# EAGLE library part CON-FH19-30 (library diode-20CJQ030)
Hirose FH19 & FH19S Series 0.5mm pitch, 0.9mm above the board, Flexible Printed Circuit & Flexible Flat Cable Connectors Features: 1. Low-profile 0.5mm pitch FPC, FFC Connectors Miniaturization of portable equipment and personal mobile devices has created increased demand for a low profile, high density, and high reliability connectors. *The design of this connector has been made thinner and smaller, with a height of 0.9mm and width of 3mm. [As of August 2002, this is the smallest connector of this type available on the market !] *PCB footprint: Reduced approximately 48% (as compared with Hirose Electric's 0.5mm pitch FH12 Series connectors) *Connector weight: Reduced approximately 78% (as compared with Hirose Electric's 0.5mm pitch FH12 Series connectors) 2. Conductive traces on the PCB can be designed to run under the connector All bottom surface of the connector is solid, without any exposure of the contact. 3. Proven Flip-Lock Actuator System assures easy and reliable operation Rotating actuator permits easy insertion and reliable connection with the FPC & FFC. Tactile sensation confirms complete mechanical locking of the actuator and the electrical connection. 4. Accepts 0.2mm & 0.3mm thick FPC, FFC Accepts 0.2mm & 0.3mm thick FPC, FFC, easy inserted in the connector. The connector will also terminate successfully with 0.2mm thick Flat Flexible Cable (FFC). 5. Designed for placement with automatic equipment Packaged in embossed tape, on reel. One reel contains 5,000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
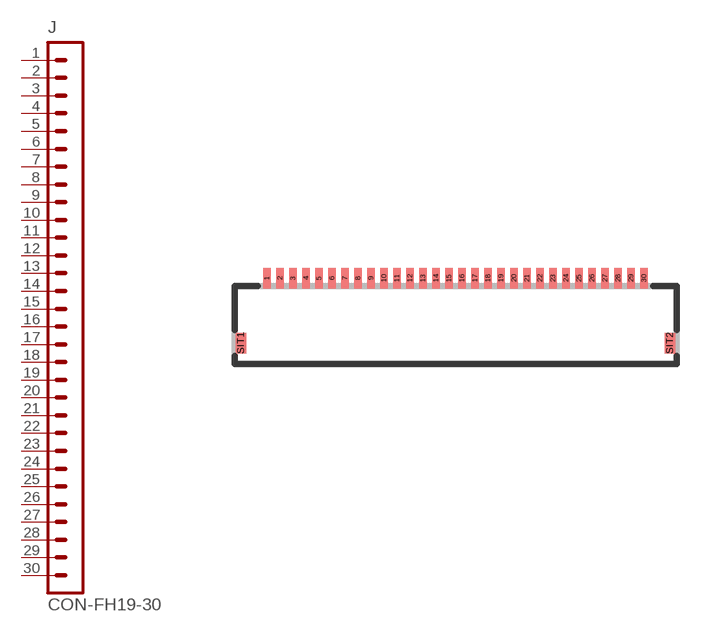
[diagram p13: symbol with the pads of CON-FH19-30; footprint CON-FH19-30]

Designator prefix J

## CON-FH19-30  [CON-FH19-30]
1  1  pas
2  2  pas
3  3  pas
4  4  pas
5  5  pas
6  6  pas
7  7  pas
8  8  pas
9  9  pas
10  10  pas
11  11  pas
12  12  pas
13  13  pas
14  14  pas
15  15  pas
16  16  pas
17  17  pas
18  18  pas
19  19  pas
20  20  pas
21  21  pas
22  22  pas
23  23  pas
24  24  pas
25  25  pas
26  26  pas
27  27  pas
28  28  pas
29  29  pas
30  30  pas

## Footprint CON-FH19-30 (pad centres in mm)
Hirose FH19 30pin 0.5mm pitch FPC/FFC connector
smd 0.3 x 0.8: 1 -7.25,0; 2 -6.75,0; 3 -6.25,0; 4 -5.75,0; 5 -5.25,0; 6 -4.75,0; 7 -4.25,0; 8 -3.75,0; 9 -3.25,0; 10 -2.75,0; 11 -2.25,0; 12 -1.75,0; 13 -1.25,0; 14 -0.75,0; 15 -0.25,0; 16 0.25,0; 17 0.75,0; 18 1.25,0; 19 1.75,0; 20 2.25,0; 21 2.75,0; 22 3.25,0; 23 3.75,0; 24 4.25,0; 25 4.75,0; 26 5.25,0; 27 5.75,0; 28 6.25,0; 29 6.75,0; 30 7.25,0
smd 0.4 x 0.8: SIT1 -8.25,-2.5; SIT2 8.25,-2.5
